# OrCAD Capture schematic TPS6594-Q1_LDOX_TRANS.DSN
size Custom; title: TPS6594-Q1 Power Management IC (PMIC) for Processors with; rev: 1.0; note: Datasheet: SLVSEA7     EVM: SLVUBT0A; note: Synchronous Step Down Converter
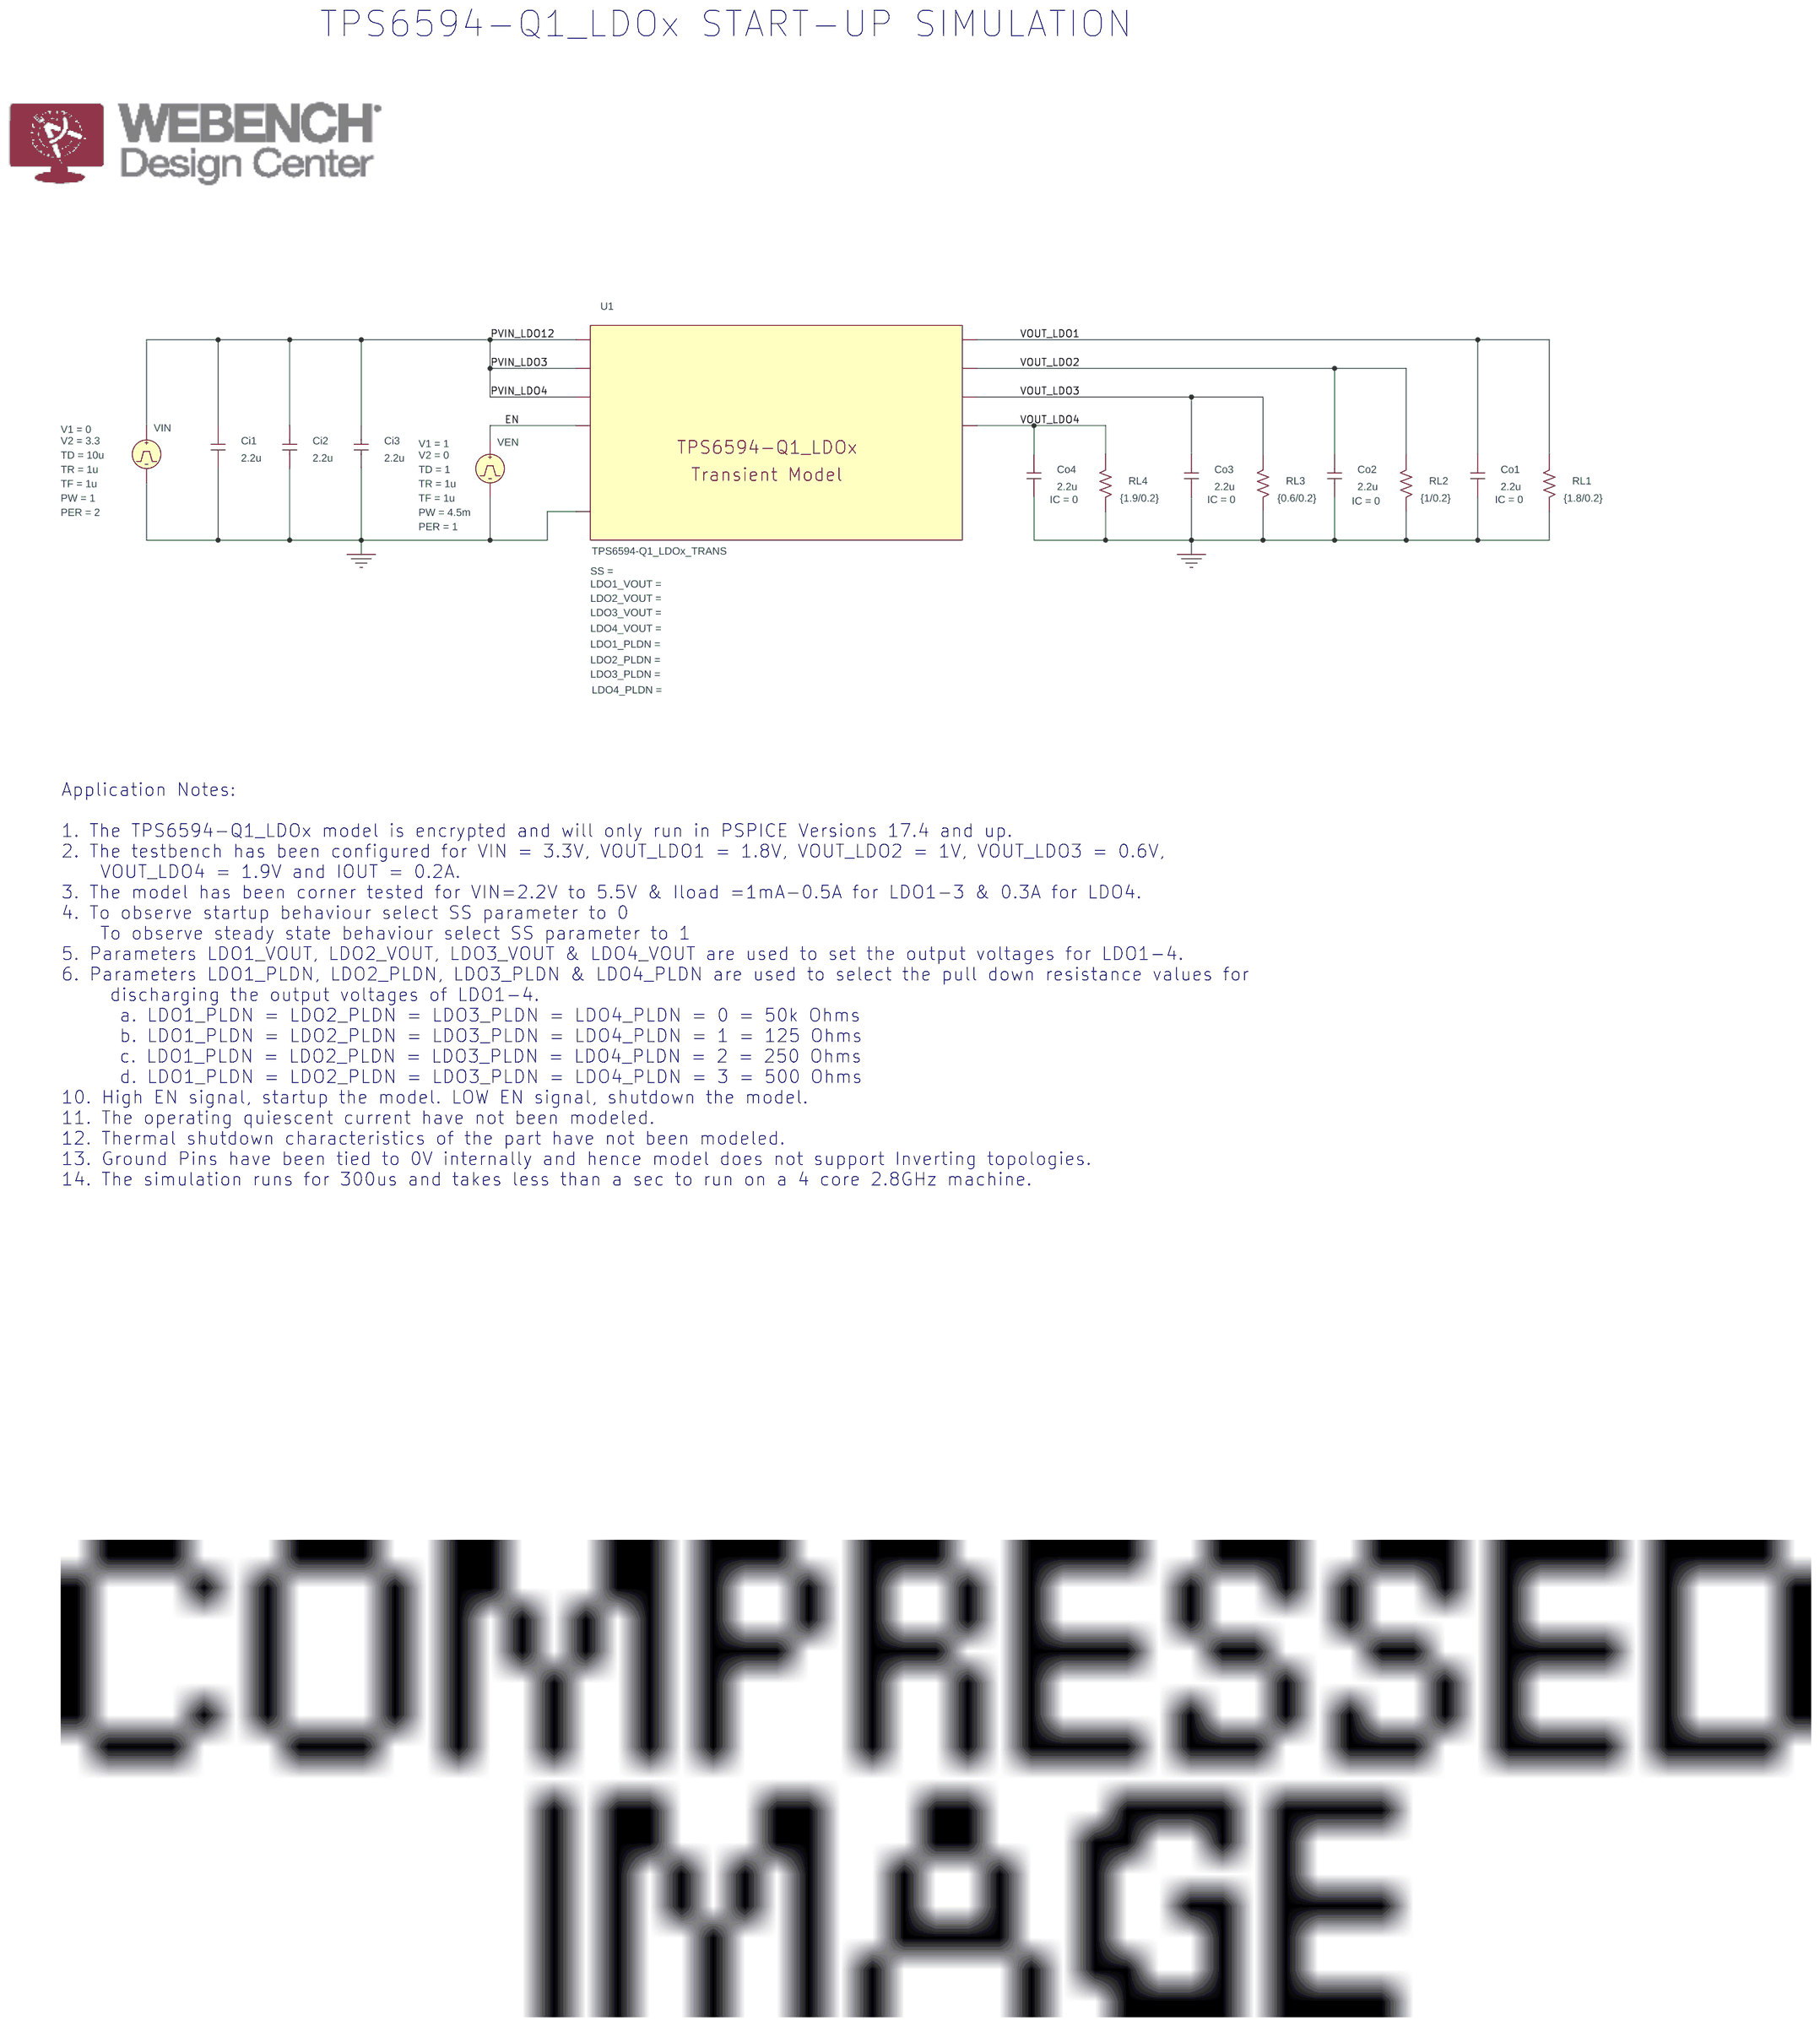
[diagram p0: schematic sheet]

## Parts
Ci1  2.2u  [RAD/CK05]
Ci2  2.2u  [RAD/CK05]
Ci3  2.2u  [RAD/CK05]
Co1  2.2u  [RAD/CK05]
Co2  2.2u  [RAD/CK05]
Co3  2.2u  [RAD/CK05]
Co4  2.2u  [RAD/CK05]
RL1  {1.8/0.2}  [AX/RC05]
RL2  {1/0.2}  [AX/RC05]
RL3  {0.6/0.2}  [AX/RC05]
RL4  {1.9/0.2}  [AX/RC05]
U1  TPS6594-Q1_LDOx_TRANS
VEN  VPULSE
VIN  VPULSE

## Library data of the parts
Ci1-Ci3 = C
Co1-Co4 = C: IC: 0
RL1-RL4 = R
U1 = TPS6594-Q1_LDOx_TRANS
VEN = VPULSE: PER: 1; PW: 4.5m; TD: 1; TF: 1u; TR: 1u; V1: 1; V2: 0
VIN = VPULSE: PER: 2; PW: 1; TD: 10u; TF: 1u; TR: 1u; V1: 0; V2: 3.3

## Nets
PVIN_LDO12: Ci1.2 Ci2.2 Ci3.2 U1.PVIN_LDO3 U1.PVIN_LDO4 U1.PVIN_LDO12 VIN.1(+)
0: Ci1.1 Ci2.1 Ci3.1 Co1.2 Co2.2 Co3.2 Co4.2 RL1.2 RL2.2 RL3.2 RL4.2 U1.GND VEN.2(-) VIN.2(-)
EN: U1.EN VEN.1(+)
VOUT_LDO1: Co1.1 RL1.1 U1.VOUT_LDO1
VOUT_LDO2: Co2.1 RL2.1 U1.VOUT_LDO2
VOUT_LDO3: Co3.1 RL3.1 U1.VOUT_LDO3
VOUT_LDO4: Co4.1 RL4.1 U1.VOUT_LDO4

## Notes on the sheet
- TPS6594-Q1_LDOx START-UP SIMULATION
- Application Notes:
  1. The TPS6594-Q1_LDOx model is encrypted and will only run in PSPICE Versions 17.4 and up.
  2. The testbench has been configured for VIN = 3.3V, VOUT_LDO1 = 1.8V, VOUT_LDO2 = 1V, VOUT_LDO3 = 0.6V,
      VOUT_LDO4 = 1.9V and IOUT = 0.2A.
  3. The model has been corner tested for VIN=2.2V to 5.5V & Iload =1mA-0.5A for LDO1-3 & 0.3A for LDO4.
  4. To observe startup behaviour select SS parameter to 0
      To observe steady state behaviour select SS parameter to 1
  5. Parameters LDO1_VOUT, LDO2_VOUT, LDO3_VOUT & LDO4_VOUT are used to set the output voltages for LDO1-4.
  6. Parameters LDO1_PLDN, LDO2_PLDN, LDO3_PLDN & LDO4_PLDN are used to select the pull down resistance values for
       discharging the output voltages of LDO1-4.
        a. LDO1_PLDN = LDO2_PLDN = LDO3_PLDN = LDO4_PLDN = 0 = 50k Ohms
        b. LDO1_PLDN = LDO2_PLDN = LDO3_PLDN = LDO4_PLDN = 1 = 125 Ohms
        c. LDO1_PLDN = LDO2_PLDN = LDO3_PLDN = LDO4_PLDN = 2 = 250 Ohms
        d. LDO1_PLDN = LDO2_PLDN = LDO3_PLDN = LDO4_PLDN = 3 = 500 Ohms
  10. High EN signal, startup the model. LOW EN signal, shutdown the model.
  11. The operating quiescent current have not been modeled.
  12. Thermal shutdown characteristics of the part have not been modeled.
  13. Ground Pins have been tied to 0V internally and hence model does not support Inverting topologies.
  14. The simulation runs for 300us and takes less than a sec to run on a 4 core 2.8GHz machine.
